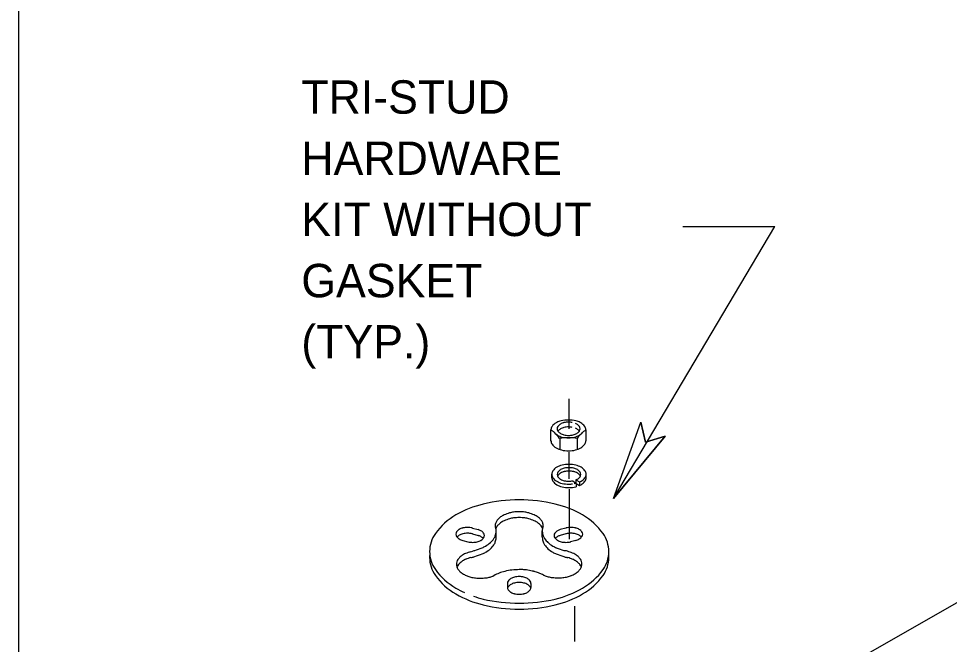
# Model space of a CAD drawing. Extents: x -224.9 to -217.6, y 224 to 234.
# Drawn here: x -221.263 to -219.59, y 229.156 to 230.281 of the extents above; entities that cross this region are included whole.
import ezdxf

# ---------------------------------------------------------------- set-up
doc = ezdxf.new("R2010")
doc.units = 0
for name, color, linetype in [('DETL-DIMS', 7, 'Continuous'), ('DETL-LINE', 7, 'Continuous'), ('DETL-NOTE', 7, 'Continuous')]:
    doc.layers.add(name, color=color, linetype=linetype)

msp = doc.modelspace()

# ---------------------------------------------------------------- linework, layer by layer
at = {"layer": 'DETL-DIMS'}
for p, q in [((-220.1937, 229.4188), (-219.9037, 229.9072)), ((-220.0691, 229.9072), (-219.9037, 229.9072)), ((-220.2736, 229.5438), (-220.2736, 229.5976)), ((-220.1937, 229.4188), (-220.1447, 229.5555)), ((-220.1362, 229.5197), (-220.1447, 229.5555)), ((-220.1937, 229.4188), (-220.1009, 229.5305)), ((-220.1009, 229.5305), (-220.1362, 229.5197)), ((-220.2736, 229.454), (-220.2736, 229.5016)), ((-220.2729, 229.3452), (-220.2729, 229.4354)), ((-220.2631, 229.1613), (-220.2631, 229.2252))]:
    msp.add_line(p, q, dxfattribs=at)
msp.add_lwpolyline([(-220.1009, 229.5305), (-220.1937, 229.4188), (-220.1447, 229.5555), (-220.1362, 229.5197)], close=True, dxfattribs=at)
at = {"layer": 'DETL-LINE'}
for p, q in [((-221.2625, 234.0154), (-221.2625, 227.5768)), ((-220.3061, 229.5217), (-220.3061, 229.5421)), ((-220.2431, 229.5223), (-220.2431, 229.5418)), ((-220.2904, 229.5261), (-220.2904, 229.5067)), ((-220.2588, 229.5261), (-220.2588, 229.5067)), ((-220.3047, 229.4559), (-220.3047, 229.4621)), ((-220.267, 229.4503), (-220.2609, 229.4456)), ((-220.2612, 229.4519), (-220.2546, 229.4483)), ((-220.2612, 229.4519), (-220.2612, 229.4459)), ((-220.243, 229.4559), (-220.243, 229.4621)), ((-220.2609, 229.4456), (-220.2645, 229.4451)), ((-220.2609, 229.4456), (-220.2609, 229.4397)), ((-220.2609, 229.4454), (-220.2546, 229.442)), ((-220.2546, 229.4483), (-220.2546, 229.442)), ((-220.4469, 229.3653), (-220.4368, 229.3627)), ((-220.4469, 229.3548), (-220.4368, 229.3521)), ((-220.4044, 229.3497), (-220.4044, 229.3602)), ((-220.3217, 229.3497), (-220.3217, 229.3602)), ((-220.2793, 229.3653), (-220.2893, 229.3627)), ((-220.2793, 229.3548), (-220.2893, 229.3521)), ((-220.4645, 229.3431), (-220.4553, 229.3407)), ((-220.2616, 229.3431), (-220.2708, 229.3407)), ((-220.4503, 229.3229), (-220.4443, 229.3248)), ((-220.3842, 229.2659), (-220.3842, 229.2587)), ((-220.342, 229.2659), (-220.342, 229.2587)), ((-219.4936, 229.2786), (-220.172, 228.892))]:
    msp.add_line(p, q, dxfattribs=at)
for centre, radius, start, end in [((-220.2854, 229.5348), 0.0229, 120, 144.3429), ((-220.2789, 229.5236), 0.0359, 118.0851, 120), ((-220.279, 229.5209), 0.0382, 103.4495, 116.0157), ((-220.2814, 229.5392), 0.0151, 120, 144.3429), ((-220.2772, 229.5318), 0.0236, 103.4495, 120), ((-220.2745, 229.502), 0.0576, 90, 103.4495), ((-220.2744, 229.5201), 0.0357, 90, 103.4495), ((-220.2745, 229.502), 0.0576, 76.5505, 90), ((-220.2756, 229.5244), 0.0315, 75.6618, 87.6727), ((-220.2712, 229.5282), 0.0267, 64.467, 70.2289), ((-220.27, 229.5209), 0.0382, 64.5132, 76.5505), ((-220.2673, 229.5392), 0.0151, 35.6571, 60), ((-220.2704, 229.5236), 0.0359, 60, 63.3228), ((-220.2639, 229.5348), 0.0229, 35.6571, 60), ((-220.2951, 229.5418), 0.0109, 144.3429, 180), ((-220.2951, 229.5418), 0.0109, 180, 180.5953), ((-220.3363, 229.4968), 0.0542, 50.5728, 56.0163), ((-220.3357, 229.4964), 0.0542, 37.8438, 51.2933), ((-220.2843, 229.5501), 0.0204, 218.3818, 240), ((-220.2879, 229.5439), 0.00716, 144.3429, 180), ((-220.2879, 229.5439), 0.00716, 180, 215.6571), ((-220.2814, 229.5485), 0.0151, 215.6571, 240), ((-220.2814, 229.5305), 0.0151, 120, 143.4298), ((-220.2772, 229.5231), 0.0236, 103.4495, 120), ((-220.2772, 229.5559), 0.0236, 240, 256.5505), ((-220.2744, 229.5114), 0.0357, 90, 103.4495), ((-220.2756, 229.5156), 0.0315, 75.6618, 87.6727), ((-220.2715, 229.5559), 0.0236, 283.4495, 300), ((-220.2712, 229.5195), 0.0267, 64.467, 70.2289), ((-220.2673, 229.5305), 0.0151, 36.5702, 60), ((-220.2673, 229.5485), 0.0151, 300, 324.3429), ((-220.2135, 229.4964), 0.0542, 128.7067, 142.1562), ((-220.2608, 229.5439), 0.00716, 0, 35.6571), ((-220.2608, 229.5439), 0.00716, 324.3429, 360), ((-220.2651, 229.5501), 0.0204, 300, 319.7392), ((-220.2135, 229.4964), 0.0542, 123.2632, 128.7067), ((-220.2541, 229.5418), 0.0109, 0, 35.6571), ((-220.2541, 229.5418), 0.0109, 359.4047, 360), ((-220.2951, 229.5224), 0.0109, 181.3029, 215.6571), ((-220.2785, 229.5601), 0.032, 240, 256.5505), ((-220.3213, 229.5076), 0.0359, 31.0705, 37.8438), ((-220.2747, 229.449), 0.0787, 90, 101.5646), ((-220.2747, 229.576), 0.0484, 256.5505, 270), ((-220.2744, 229.5676), 0.0357, 256.5505, 270), ((-220.2747, 229.576), 0.0484, 270, 283.4495), ((-220.2747, 229.449), 0.0787, 78.3837, 90), ((-220.2744, 229.5676), 0.0357, 270, 283.4495), ((-220.2709, 229.5601), 0.032, 283.4495, 300), ((-220.228, 229.5076), 0.0359, 142.1562, 148.9295), ((-220.2541, 229.5224), 0.0109, 324.3429, 359.5811), ((-220.2854, 229.5294), 0.0229, 215.6571, 240), ((-220.2789, 229.5406), 0.0359, 240, 256.5505), ((-220.2746, 229.5584), 0.0542, 256.5505, 270), ((-220.2746, 229.5584), 0.0542, 270, 283.4495), ((-220.2704, 229.5406), 0.0359, 283.4495, 300), ((-220.2639, 229.5294), 0.0229, 300, 324.3429), ((-220.294, 229.4621), 0.0107, 144.3429, 180), ((-220.2844, 229.4552), 0.0225, 120, 144.3429), ((-220.278, 229.4441), 0.0353, 103.4495, 120), ((-220.281, 229.4569), 0.0155, 120, 144.3429), ((-220.2779, 229.5096), 0.0332, 251.0308, 251.1847), ((-220.2766, 229.4493), 0.0243, 103.4495, 120), ((-220.2766, 229.4431), 0.0243, 103.4495, 120), ((-220.2738, 229.4266), 0.0533, 90, 103.4495), ((-220.2737, 229.4372), 0.0367, 90, 103.4495), ((-220.2737, 229.4311), 0.0367, 90, 103.4495), ((-220.2738, 229.4266), 0.0533, 76.5505, 90), ((-220.2737, 229.4372), 0.0367, 76.5505, 90), ((-220.2737, 229.4311), 0.0367, 76.5505, 90), ((-220.2708, 229.4493), 0.0243, 60, 76.5505), ((-220.2708, 229.4431), 0.0243, 60, 76.5505), ((-220.2697, 229.4441), 0.0353, 60, 76.5505), ((-220.27, 229.5096), 0.0332, 288.7445, 288.9692), ((-220.2664, 229.4569), 0.0155, 35.6571, 60), ((-220.2633, 229.4552), 0.0225, 35.6571, 60), ((-220.2536, 229.4621), 0.0107, 0, 35.6571), ((-220.294, 229.4621), 0.0107, 180, 215.6571), ((-220.294, 229.4559), 0.0107, 178.0522, 180), ((-220.294, 229.4559), 0.0107, 180, 215.6571), ((-220.2844, 229.469), 0.0225, 215.6571, 240), ((-220.2844, 229.4628), 0.0225, 215.6571, 240), ((-220.2876, 229.4616), 0.00736, 144.3429, 180), ((-220.2876, 229.4616), 0.00736, 180, 215.6571), ((-220.2876, 229.4555), 0.00736, 144.3429, 155.3574), ((-220.281, 229.4508), 0.0155, 120, 144.3429), ((-220.281, 229.4664), 0.0155, 215.6571, 240), ((-220.2766, 229.474), 0.0243, 240, 256.5505), ((-220.2737, 229.4861), 0.0367, 256.5505, 270), ((-220.275, 229.4817), 0.0323, 272.3273, 284.3382), ((-220.2705, 229.4777), 0.0274, 289.7711, 295.533), ((-220.2664, 229.4508), 0.0155, 35.6571, 60), ((-220.2664, 229.4664), 0.0155, 300, 324.3429), ((-220.2598, 229.4616), 0.00736, 360, 35.6571), ((-220.2598, 229.4616), 0.00736, 324.3429, 0), ((-220.2598, 229.4555), 0.00736, 24.6426, 35.6571), ((-220.2633, 229.469), 0.0225, 300, 324.3429), ((-220.2633, 229.4628), 0.0225, 300, 324.3429), ((-220.2536, 229.4621), 0.0107, 324.3429, 360), ((-220.2536, 229.4559), 0.0107, 324.3429, 360), ((-220.2536, 229.4559), 0.0107, 0, 1.3736), ((-220.278, 229.48), 0.0353, 240, 256.5505), ((-220.278, 229.4739), 0.0353, 240, 256.5505), ((-220.2738, 229.4975), 0.0533, 256.5505, 270), ((-220.2738, 229.4914), 0.0533, 256.5505, 270), ((-220.2752, 229.4931), 0.0489, 271.5685, 279.4574), ((-220.2738, 229.4914), 0.0533, 270, 283.4495), ((-220.2697, 229.4739), 0.0353, 283.4495, 284.3417), ((-220.2693, 229.4837), 0.0383, 292.5661, 296.8707), ((-220.2697, 229.4739), 0.0353, 295.2053, 300), ((-220.3849, 229.2295), 0.184, 103.4495, 120), ((-220.3631, 229.1381), 0.278, 90, 103.4495), ((-220.3631, 229.1381), 0.278, 76.5505, 90), ((-220.3412, 229.2295), 0.184, 60, 76.5505), ((-220.4182, 229.2872), 0.1175, 120, 144.3429), ((-220.3821, 229.364), 0.0257, 132.1714, 146.1064), ((-220.3768, 229.3582), 0.0336, 120, 132.1714), ((-220.3796, 229.3629), 0.0281, 111.7247, 120), ((-220.3247, 229.2254), 0.1762, 108.4215, 111.7247), ((-220.3692, 229.3587), 0.0356, 96.7247, 108.4215), ((-220.3692, 229.3482), 0.0356, 96.7247, 108.4215), ((-220.365, 229.3236), 0.0711, 88.4495, 96.7247), ((-220.365, 229.313), 0.0711, 88.4495, 96.7247), ((-220.3612, 229.3236), 0.0711, 83.2753, 91.5505), ((-220.3612, 229.313), 0.0711, 83.2753, 91.5505), ((-220.357, 229.3587), 0.0356, 71.5785, 83.2753), ((-220.357, 229.3482), 0.0356, 71.5785, 83.2753), ((-220.4014, 229.2254), 0.1762, 68.2753, 71.5785), ((-220.3466, 229.3629), 0.0281, 60, 68.2753), ((-220.3494, 229.3582), 0.0336, 47.8286, 60), ((-220.3441, 229.364), 0.0257, 33.8936, 47.8286), ((-220.308, 229.2872), 0.1175, 35.6571, 60), ((-220.4559, 229.33), 0.0365, 90, 103.4495), ((-220.4559, 229.33), 0.0365, 76.5505, 90), ((-220.3955, 229.3703), 0.0107, 162.1714, 183.5527), ((-220.3878, 229.3708), 0.0185, 183.5527, 194.084), ((-220.4296, 229.3574), 0.0257, 17.4025, 23.3165), ((-220.3878, 229.3678), 0.0189, 146.1064, 162.1714), ((-220.4295, 229.3568), 0.0256, 17.6287, 21.814), ((-220.3878, 229.3573), 0.0189, 146.1064, 156.9278), ((-220.3821, 229.3535), 0.0257, 132.1714, 146.1064), ((-220.3768, 229.3476), 0.0336, 120, 132.1714), ((-220.3796, 229.3524), 0.0281, 111.7247, 120), ((-220.3247, 229.2149), 0.1762, 108.4215, 111.7247), ((-220.4014, 229.2149), 0.1762, 68.2753, 71.5785), ((-220.3466, 229.3524), 0.0281, 60, 68.2753), ((-220.3494, 229.3476), 0.0336, 47.8286, 60), ((-220.3441, 229.3535), 0.0257, 33.8936, 47.8286), ((-220.3384, 229.3678), 0.0189, 17.8286, 33.8936), ((-220.3384, 229.3573), 0.0189, 23.0722, 33.8936), ((-220.2966, 229.3574), 0.0257, 156.6835, 162.5975), ((-220.2966, 229.3574), 0.0257, 156.6835, 162.5975), ((-220.3306, 229.3703), 0.0107, 356.4472, 17.8286), ((-220.3384, 229.3708), 0.0185, 349.9031, 356.4472), ((-220.2703, 229.33), 0.0365, 90, 103.4495), ((-220.2703, 229.33), 0.0365, 76.5505, 90), ((-220.4684, 229.3232), 0.0557, 144.3429, 180), ((-220.4697, 229.3543), 0.00731, 144.3429, 180), ((-220.4697, 229.3543), 0.00731, 180, 215.6571), ((-220.4631, 229.3496), 0.0154, 120, 144.3429), ((-220.4631, 229.359), 0.0154, 215.6571, 240), ((-220.4631, 229.339), 0.0154, 120, 139.6335), ((-220.4588, 229.342), 0.0241, 103.4495, 120), ((-220.4588, 229.3315), 0.0241, 103.4495, 120), ((-220.4559, 229.3195), 0.0365, 90, 103.4495), ((-220.4559, 229.3195), 0.0365, 76.5505, 90), ((-220.453, 229.342), 0.0241, 75.1944, 76.5505), ((-220.453, 229.3315), 0.0241, 75.1944, 76.5505), ((-220.444, 229.3396), 0.0241, 60, 72.7643), ((-220.444, 229.3291), 0.0241, 60, 72.7643), ((-220.4396, 229.3472), 0.0154, 35.6571, 60), ((-220.4396, 229.3366), 0.0154, 40.3665, 60), ((-220.433, 229.3519), 0.00731, 0, 35.6571), ((-220.433, 229.3519), 0.00731, 324.3429, 360), ((-220.4261, 229.358), 0.021, 326.1862, 342.1714), ((-220.4429, 229.3634), 0.0386, 342.1714, 353.9334), ((-220.4186, 229.3608), 0.0142, 353.9334, 17.4025), ((-220.4187, 229.3602), 0.0143, 0.0001, 17.6287), ((-220.4187, 229.3497), 0.0143, 353.9054, 0.0001), ((-220.3075, 229.3608), 0.0142, 162.5975, 186.0666), ((-220.3075, 229.3608), 0.0142, 162.5975, 186.0666), ((-220.2833, 229.3634), 0.0386, 186.0666, 197.8286), ((-220.2833, 229.3634), 0.0386, 186.0666, 197.8286), ((-220.3075, 229.3497), 0.0143, 179.9999, 186.0946), ((-220.3001, 229.358), 0.021, 197.8286, 213.8138), ((-220.3001, 229.358), 0.021, 197.8286, 213.8138), ((-220.2931, 229.3519), 0.00731, 144.3429, 180), ((-220.2931, 229.3519), 0.00731, 180, 215.6571), ((-220.2866, 229.3472), 0.0154, 120, 144.3429), ((-220.2866, 229.3366), 0.0154, 120, 139.6335), ((-220.2822, 229.3396), 0.0241, 107.2357, 120), ((-220.2822, 229.3291), 0.0241, 107.2357, 120), ((-220.2731, 229.342), 0.0241, 103.4495, 104.8056), ((-220.2731, 229.3315), 0.0241, 103.4495, 104.8056), ((-220.2703, 229.3195), 0.0365, 90, 103.4495), ((-220.2703, 229.3195), 0.0365, 76.5505, 90), ((-220.2674, 229.342), 0.0241, 60, 76.5505), ((-220.2674, 229.3315), 0.0241, 60, 76.5505), ((-220.263, 229.3496), 0.0154, 35.6571, 60), ((-220.263, 229.339), 0.0154, 40.3665, 60), ((-220.263, 229.359), 0.0154, 300, 324.3429), ((-220.2564, 229.3543), 0.00731, 360, 35.6571), ((-220.2564, 229.3543), 0.00731, 324.3429, 360), ((-220.2578, 229.3232), 0.0557, 0, 35.6571), ((-220.4588, 229.3666), 0.0241, 240, 256.1867), ((-220.4497, 229.3642), 0.0241, 255.8168, 256.5505), ((-220.4469, 229.3762), 0.0365, 256.5505, 270), ((-220.4469, 229.3762), 0.0365, 270, 283.4495), ((-220.444, 229.3642), 0.0241, 283.4495, 300), ((-220.4396, 229.3566), 0.0154, 300, 324.3429), ((-220.4478, 229.3754), 0.0489, 291.7247, 300), ((-220.4486, 229.3766), 0.0503, 300, 312.1714), ((-220.4403, 229.3675), 0.038, 312.1714, 326.1862), ((-220.4404, 229.3565), 0.0382, 312.1714, 326.1437), ((-220.426, 229.3468), 0.0209, 326.1437, 342.1714), ((-220.4431, 229.3523), 0.0388, 342.1714, 353.9054), ((-220.2831, 229.3523), 0.0388, 186.0946, 197.8286), ((-220.3002, 229.3468), 0.0209, 197.8286, 213.8563), ((-220.2859, 229.3675), 0.038, 213.8138, 227.8286), ((-220.2859, 229.3675), 0.038, 213.8138, 227.8286), ((-220.2858, 229.3565), 0.0382, 213.8563, 227.8286), ((-220.2776, 229.3766), 0.0503, 227.8286, 240), ((-220.2776, 229.3766), 0.0503, 227.8286, 240), ((-220.2783, 229.3754), 0.0489, 240, 248.2753), ((-220.2783, 229.3754), 0.0489, 240, 248.2753), ((-220.2866, 229.3566), 0.0154, 215.6571, 240), ((-220.2822, 229.3642), 0.0241, 240, 256.5505), ((-220.2793, 229.3762), 0.0365, 256.5505, 270), ((-220.2793, 229.3762), 0.0365, 270, 283.4495), ((-220.2764, 229.3642), 0.0241, 283.4495, 284.1832), ((-220.2674, 229.3666), 0.0241, 283.8133, 300), ((-220.4684, 229.3232), 0.0557, 180, 215.6571), ((-220.4684, 229.3127), 0.0557, 174.5836, 180), ((-220.4464, 229.2887), 0.0336, 120, 132.1714), ((-220.4484, 229.292), 0.0298, 111.7247, 120), ((-220.4007, 229.1724), 0.1585, 108.2479, 111.7247), ((-220.4548, 229.3622), 0.0388, 285.762, 287.601), ((-220.5026, 229.5128), 0.1968, 287.601, 291.7247), ((-220.5059, 229.5104), 0.2061, 287.7431, 291.7247), ((-220.4473, 229.3633), 0.0478, 291.7247, 300), ((-220.4485, 229.3654), 0.0503, 300, 312.1714), ((-220.2777, 229.3654), 0.0503, 227.8286, 240), ((-220.2789, 229.3633), 0.0478, 240, 248.2753), ((-220.2203, 229.5104), 0.2061, 248.2753, 252.2569), ((-220.2236, 229.5128), 0.1968, 248.2753, 252.399), ((-220.2236, 229.5128), 0.1968, 248.2753, 252.399), ((-220.2714, 229.3622), 0.0388, 252.399, 254.238), ((-220.2714, 229.3622), 0.0388, 252.399, 254.238), ((-220.2919, 229.2546), 0.0709, 80.3565, 81.9421), ((-220.2845, 229.298), 0.0269, 72.3032, 80.3565), ((-220.3177, 229.1941), 0.136, 68.2753, 72.3032), ((-220.2793, 229.2904), 0.0323, 60, 68.2753), ((-220.2799, 229.2893), 0.0336, 47.8286, 60), ((-220.2578, 229.3232), 0.0557, 324.3429, 360), ((-220.2578, 229.3127), 0.0557, 0, 5.4164), ((-220.4684, 229.3127), 0.0557, 180, 215.6571), ((-220.4618, 229.3002), 0.0141, 162.1714, 180), ((-220.4618, 229.3002), 0.0141, 180, 197.8286), ((-220.4587, 229.2992), 0.0174, 146.1064, 162.1714), ((-220.4518, 229.2945), 0.0257, 132.1714, 146.1064), ((-220.4518, 229.284), 0.0257, 132.1714, 146.1064), ((-220.4464, 229.2781), 0.0336, 120, 132.1714), ((-220.4484, 229.2815), 0.0298, 111.7247, 120), ((-220.4007, 229.1619), 0.1585, 108.2479, 111.7247), ((-220.4662, 229.417), 0.1058, 278.6437, 279.517), ((-220.4555, 229.3529), 0.0408, 279.517, 287.7431), ((-220.2707, 229.3529), 0.0408, 252.2569, 260.483), ((-220.2599, 229.417), 0.1058, 260.483, 261.3563), ((-220.3255, 229.1619), 0.1585, 68.2753, 71.7521), ((-220.2778, 229.2815), 0.0298, 60, 68.2753), ((-220.2797, 229.2781), 0.0336, 47.8286, 60), ((-220.2746, 229.2951), 0.0257, 33.8936, 47.8286), ((-220.2744, 229.284), 0.0257, 33.8936, 47.8286), ((-220.2677, 229.2998), 0.0174, 17.8286, 33.8936), ((-220.2646, 229.3008), 0.0141, 360, 17.8286), ((-220.2646, 229.3008), 0.0141, 342.1714, 0), ((-220.2578, 229.3127), 0.0557, 324.3429, 360), ((-220.4182, 229.3592), 0.1175, 215.6571, 240), ((-220.4587, 229.3012), 0.0174, 197.8286, 213.8936), ((-220.4587, 229.2887), 0.0174, 146.1064, 158.9259), ((-220.4518, 229.3058), 0.0257, 213.8936, 227.8286), ((-220.4464, 229.3117), 0.0336, 227.8286, 240), ((-220.4386, 229.3252), 0.0493, 240, 248.2753), ((-220.3718, 229.216), 0.0736, 103.4495, 120), ((-220.3631, 229.1794), 0.1112, 90, 103.4495), ((-220.36, 229.1745), 0.1162, 87.3973, 91.5193), ((-220.3564, 229.2536), 0.037, 80.0864, 87.3973), ((-220.4631, 228.6432), 0.6566, 79.1532, 80.0864), ((-220.3456, 229.2566), 0.0321, 74.9328, 79.1532), ((-220.3521, 229.2323), 0.0572, 71.8003, 74.9328), ((-220.4679, 228.8802), 0.4279, 70.6551, 71.8003), ((-220.3377, 229.2511), 0.0348, 64.9628, 70.6551), ((-220.3423, 229.2411), 0.0458, 60, 64.9628), ((-220.2877, 229.3258), 0.0493, 291.7247, 300), ((-220.2799, 229.3123), 0.0336, 300, 312.1714), ((-220.2746, 229.3064), 0.0257, 312.1714, 326.1064), ((-220.2677, 229.3018), 0.0174, 326.1064, 342.1714), ((-220.2675, 229.2887), 0.0174, 21.0741, 33.8936), ((-220.308, 229.3592), 0.1175, 300, 324.3429), ((-220.4182, 229.3487), 0.1175, 215.6571, 240), ((-220.4385, 229.3254), 0.0495, 248.2753, 256.5288), ((-220.4328, 229.3494), 0.0742, 256.5288, 263.2753), ((-220.4327, 229.3499), 0.0746, 263.2753, 270), ((-220.4327, 229.3608), 0.0855, 270, 276.7247), ((-220.4283, 229.3228), 0.0473, 276.7247, 285.7752), ((-220.4371, 229.354), 0.0797, 285.7752, 290.1641), ((-220.3851, 229.239), 0.047, 120, 121.9864), ((-220.3769, 229.2659), 0.00731, 144.3429, 180), ((-220.3703, 229.2612), 0.0154, 120, 144.3429), ((-220.366, 229.2536), 0.0241, 103.4495, 120), ((-220.366, 229.2431), 0.0241, 103.4495, 120), ((-220.3631, 229.2416), 0.0365, 90, 103.4495), ((-220.3631, 229.2311), 0.0365, 90, 103.4495), ((-220.3631, 229.2416), 0.0365, 76.5505, 90), ((-220.3631, 229.2311), 0.0365, 76.5505, 90), ((-220.3602, 229.2536), 0.0241, 60, 76.5505), ((-220.3602, 229.2431), 0.0241, 60, 76.5505), ((-220.3559, 229.2612), 0.0154, 35.6571, 60), ((-220.3493, 229.2659), 0.00731, 0, 35.6571), ((-220.3033, 229.3192), 0.0416, 247.3083, 248.2753), ((-220.2899, 229.3528), 0.0778, 248.2753, 254.3263), ((-220.298, 229.3242), 0.0481, 254.3263, 263.2753), ((-220.2936, 229.361), 0.0851, 263.2753, 270), ((-220.2936, 229.3505), 0.0746, 270, 276.7247), ((-220.2936, 229.35), 0.0742, 276.7247, 283.4712), ((-220.2878, 229.3261), 0.0495, 283.4712, 291.7247), ((-220.308, 229.3487), 0.1175, 300, 324.3429), ((-220.3849, 229.4168), 0.184, 240, 245.3427), ((-220.3769, 229.2587), 0.00731, 180, 215.6571), ((-220.3769, 229.2554), 0.00731, 144.3429, 167.1006), ((-220.3703, 229.2507), 0.0154, 120, 144.3429), ((-220.3703, 229.2634), 0.0154, 215.6571, 240), ((-220.366, 229.2709), 0.0241, 240, 256.5505), ((-220.3602, 229.2709), 0.0241, 283.4495, 300), ((-220.3559, 229.2507), 0.0154, 35.6571, 60), ((-220.3559, 229.2634), 0.0154, 300, 324.3429), ((-220.3493, 229.2554), 0.00731, 12.8994, 35.6571), ((-220.3493, 229.2587), 0.00731, 324.3429, 0), ((-220.3412, 229.4168), 0.184, 283.4495, 300), ((-220.3849, 229.4063), 0.184, 240, 256.5505), ((-220.3849, 229.4168), 0.184, 250.8196, 256.5505), ((-220.3631, 229.5082), 0.278, 256.5505, 270), ((-220.3631, 229.2829), 0.0365, 256.5505, 270), ((-220.3631, 229.2829), 0.0365, 270, 283.4495), ((-220.3631, 229.5082), 0.278, 270, 283.4495), ((-220.3412, 229.4063), 0.184, 283.4495, 300), ((-220.3631, 229.4977), 0.278, 256.5505, 270), ((-220.3631, 229.4977), 0.278, 270, 283.4495)]:
    msp.add_arc(centre, radius, start, end, dxfattribs=at)

# ---------------------------------------------------------------- texts
at = {"layer": 'DETL-NOTE'}
for s, p in [('TRI-STUD', (-220.7546, 230.1102)), ('HARDWARE', (-220.7546, 230.0002)), ('KIT WITHOUT', (-220.7546, 229.8902)), ('GASKET', (-220.7546, 229.7802)), ('(TYP.)', (-220.7546, 229.6702))]:
    msp.add_text(s, height=0.06, dxfattribs=at).set_placement(p)

doc.saveas('drawing.dxf')
